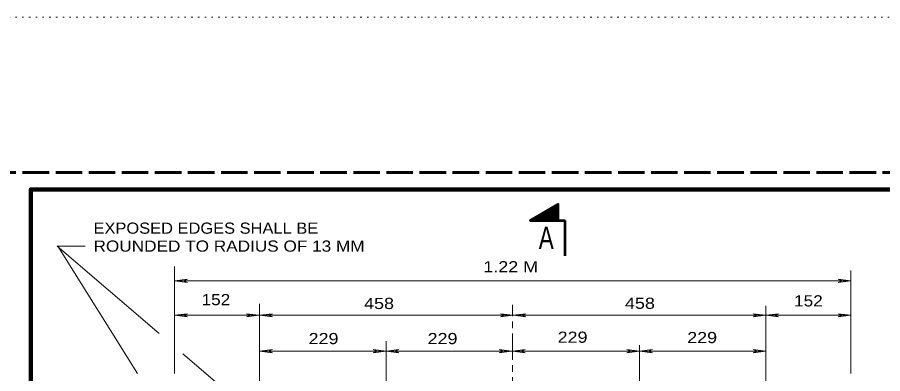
# Model space of a CAD drawing. Extents: x 312583 to 312854, y 144419 to 144597.
# Drawn here: x 312615.6 to 312674.5, y 144572.6 to 144596.8 of the extents above; entities that cross this region are included whole.
import ezdxf
from ezdxf.enums import TextEntityAlignment as Align

# ---------------------------------------------------------------- set-up
doc = ezdxf.new("R2010")
doc.units = 0
doc.header["$LTSCALE"] = 0.3
for name, pattern in [('DOTTED', [1.5, 0.3, -1.2]), ('LONG_DASH_SHORT_DASH', [9.9, 6, -1.2, 1.5, -1.2]), ('LONG_DASHED', [7.5, 6, -1.5])]:
    doc.linetypes.add(name, pattern=pattern)
for name, color, linetype, lineweight in [('1', 7, 'Continuous', 40), ('2', 7, 'Continuous', 13), ('63', 7, 'DOTTED', 13)]:
    doc.layers.add(name, color=color, linetype=linetype, lineweight=lineweight)

msp = doc.modelspace()

# ---------------------------------------------------------------- linework, layer by layer
at = {"layer": '1', "linetype": 'LONG_DASHED', "lineweight": 60}
msp.add_line((312851.75, 144586.2246), (312583.526, 144586.2246), dxfattribs=at)
at = {"layer": '1', "lineweight": 35}
for p, q in [((312652.3828, 144583.3724), (312652.0761, 144583.9014)), ((312652.3828, 144583.4184), (312652.0991, 144583.9091)), ((312652.3828, 144583.4721), (312652.1144, 144583.9244)), ((312652.3828, 144583.5181), (312652.1374, 144583.9321)), ((312652.3828, 144583.5641), (312652.1604, 144583.9474)), ((312652.3828, 144583.6178), (312652.1758, 144583.9551)), ((312652.3828, 144583.6638), (312652.2064, 144583.9704)), ((312652.3828, 144583.7098), (312652.2218, 144583.9781)), ((312652.3828, 144583.7558), (312652.2448, 144583.9934)), ((312652.3828, 144583.8094), (312652.2678, 144584.0011)), ((312652.3828, 144583.8478), (312652.2831, 144584.0164)), ((312652.3828, 144583.9014), (312652.3061, 144584.0241)), ((312652.3828, 144583.9474), (312652.3291, 144584.0394)), ((312652.3828, 144584.0011), (312652.3444, 144584.0548)), ((312652.3828, 144584.0471), (312652.3674, 144584.0624)), ((312651.2864, 144582.9661), (312651.0794, 144583.3264)), ((312651.3094, 144582.9661), (312651.1024, 144583.3341)), ((312651.3401, 144582.9661), (312651.1254, 144583.3494)), ((312651.3708, 144582.9661), (312651.1408, 144583.3648)), ((312651.4014, 144582.9661), (312651.1638, 144583.3724)), ((312651.4244, 144582.9661), (312651.1868, 144583.3878)), ((312651.4474, 144582.9661), (312651.2098, 144583.3954)), ((312651.4781, 144582.9661), (312651.2251, 144583.4108)), ((312651.5088, 144582.9661), (312651.2481, 144583.4184)), ((312651.5318, 144582.9661), (312651.2711, 144583.4338)), ((312651.5624, 144582.9661), (312651.2864, 144583.4414)), ((312651.5931, 144582.9661), (312651.3094, 144583.4568)), ((312651.6161, 144582.9661), (312651.3324, 144583.4644)), ((312651.6468, 144582.9661), (312651.3478, 144583.4798)), ((312651.6774, 144582.9661), (312651.3708, 144583.4874)), ((312651.7004, 144582.9661), (312651.3938, 144583.5028)), ((312651.7311, 144582.9738), (312651.4091, 144583.5181)), ((312651.7541, 144582.9661), (312651.4398, 144583.5258)), ((312651.7848, 144582.9661), (312651.4551, 144583.5411)), ((312651.8078, 144582.9661), (312651.4781, 144583.5488)), ((312651.8384, 144582.9661), (312651.5011, 144583.5641)), ((312651.8691, 144582.9661), (312651.5164, 144583.5718)), ((312651.8998, 144582.9661), (312651.5394, 144583.5871)), ((312651.9228, 144582.9661), (312651.5624, 144583.5948)), ((312651.9458, 144582.9661), (312651.5778, 144583.6101)), ((312651.9764, 144582.9738), (312651.6008, 144583.6178)), ((312652.0071, 144582.9661), (312651.6238, 144583.6331)), ((312652.0301, 144582.9661), (312651.6391, 144583.6408)), ((312652.0608, 144582.9661), (312651.6621, 144583.6561)), ((312652.0914, 144582.9661), (312651.6851, 144583.6714)), ((312652.1144, 144582.9661), (312651.7081, 144583.6791)), ((312652.1451, 144582.9661), (312651.7234, 144583.6944)), ((312652.1758, 144582.9661), (312651.7464, 144583.7098)), ((312652.1988, 144582.9738), (312651.7694, 144583.7174)), ((312652.2294, 144582.9738), (312651.7848, 144583.7328)), ((312652.2524, 144582.9661), (312651.8078, 144583.7404)), ((312652.2831, 144582.9661), (312651.8308, 144583.7558)), ((312652.3061, 144582.9661), (312651.8461, 144583.7634)), ((312652.3368, 144582.9661), (312651.8691, 144583.7788)), ((312652.3674, 144582.9661), (312651.8921, 144583.7864)), ((312652.3828, 144582.9891), (312651.9074, 144583.8018)), ((312652.3828, 144583.0428), (312651.9381, 144583.8094)), ((312652.3828, 144583.0811), (312651.9534, 144583.8248)), ((312652.3828, 144583.1348), (312651.9764, 144583.8324)), ((312652.3828, 144583.1808), (312651.9994, 144583.8478)), ((312652.3828, 144583.2268), (312652.0148, 144583.8631)), ((312652.3828, 144583.2728), (312652.0378, 144583.8708)), ((312652.3828, 144583.3264), (312652.0608, 144583.8861)), ((312650.4814, 144582.9661), (312650.4814, 144582.9814)), ((312650.5121, 144582.9661), (312650.5044, 144582.9891)), ((312650.5428, 144582.9661), (312650.5198, 144583.0044)), ((312650.5658, 144582.9661), (312650.5428, 144583.0121)), ((312650.5964, 144582.9661), (312650.5658, 144583.0274)), ((312650.6194, 144582.9661), (312650.5811, 144583.0351)), ((312650.6501, 144582.9661), (312650.6041, 144583.0504)), ((312650.6808, 144582.9661), (312650.6271, 144583.0581)), ((312650.7114, 144582.9661), (312650.6424, 144583.0734)), ((312650.7344, 144582.9661), (312650.6654, 144583.0811)), ((312650.7574, 144582.9661), (312650.6884, 144583.0964)), ((312650.7881, 144582.9661), (312650.7114, 144583.1041)), ((312650.8111, 144582.9661), (312650.7268, 144583.1194)), ((312650.8418, 144582.9661), (312650.7498, 144583.1348)), ((312650.8724, 144582.9661), (312650.7728, 144583.1424)), ((312650.9031, 144582.9661), (312650.7881, 144583.1578)), ((312650.9261, 144582.9661), (312650.8111, 144583.1731)), ((312650.9568, 144582.9661), (312650.8341, 144583.1808)), ((312650.9798, 144582.9661), (312650.8494, 144583.1961)), ((312651.0104, 144582.9661), (312650.8724, 144583.2038)), ((312651.0411, 144582.9661), (312650.8954, 144583.2191)), ((312651.0641, 144582.9661), (312650.9108, 144583.2268)), ((312651.0948, 144582.9661), (312650.9414, 144583.2421)), ((312651.1178, 144582.9661), (312650.9568, 144583.2498)), ((312651.1484, 144582.9661), (312650.9798, 144583.2651)), ((312651.1791, 144582.9661), (312651.0028, 144583.2728)), ((312651.2021, 144582.9661), (312651.0181, 144583.2881)), ((312651.2328, 144582.9661), (312651.0411, 144583.2958)), ((312651.2558, 144582.9661), (312651.0641, 144583.3111))]:
    msp.add_line(p, q, dxfattribs=at)
at = {"layer": '1', "lineweight": 53}
for p in [(312652.3828, 144582.9661), (312652.8581, 144580.5741)]:
    msp.add_line(p, (312652.8581, 144582.9661), dxfattribs=at)
at = {"layer": '1', "lineweight": 158}
msp.add_lwpolyline([(312616.5, 144423.1446), (312616.5, 144585.0846), (312849, 144585.0846)], dxfattribs=at)
at = {"layer": '1', "lineweight": 53}
msp.add_lwpolyline([(312652.3828, 144582.9661), (312652.3828, 144584.0778), (312650.4661, 144582.9661)], close=True, dxfattribs=at)
at = {"layer": '2'}
for p, q in [((312618.3476, 144581.2339), (312623.7708, 144572.5701)), ((312626.2931, 144572.5701), (312626.2931, 144579.8458)), ((312672.2931, 144572.5701), (312672.2931, 144579.5698)), ((312626.2931, 144578.8721), (312627.1594, 144578.9794)), ((312626.2931, 144578.8721), (312672.2931, 144578.8721)), ((312626.2931, 144578.8721), (312627.1594, 144578.7648)), ((312627.1594, 144578.9794), (312626.8834, 144578.8721)), ((312627.1594, 144578.7648), (312626.8834, 144578.8721)), ((312671.4268, 144578.9794), (312671.7028, 144578.8721)), ((312672.2931, 144578.8721), (312671.4268, 144578.9794)), ((312671.4268, 144578.7648), (312671.7028, 144578.8721)), ((312672.2931, 144578.8721), (312671.4268, 144578.7648)), ((312632.0738, 144566.5824), (312632.0738, 144577.3004)), ((312666.4971, 144566.4981), (312666.4971, 144577.1778)), ((312626.2931, 144576.5261), (312627.1594, 144576.6334)), ((312626.2931, 144576.5261), (312632.0431, 144576.5261)), ((312626.2931, 144576.5261), (312627.1594, 144576.4188)), ((312627.1594, 144576.6334), (312626.8834, 144576.5261)), ((312627.1594, 144576.4188), (312626.8834, 144576.5261)), ((312631.1768, 144576.6334), (312631.4528, 144576.5261)), ((312632.0431, 144576.5261), (312631.1768, 144576.6334)), ((312631.1768, 144576.4188), (312631.4528, 144576.5261)), ((312632.0431, 144576.5261), (312631.1768, 144576.4188)), ((312632.0738, 144576.5261), (312632.9401, 144576.6334)), ((312632.0738, 144576.5261), (312649.3161, 144576.5261)), ((312632.0738, 144576.5261), (312632.9401, 144576.4188)), ((312632.9401, 144576.6334), (312632.6641, 144576.5261)), ((312632.9401, 144576.4188), (312632.6641, 144576.5261)), ((312648.4498, 144576.6334), (312648.7258, 144576.5261)), ((312649.3161, 144576.5261), (312648.4498, 144576.6334)), ((312648.4498, 144576.4188), (312648.7258, 144576.5261)), ((312649.3161, 144576.5261), (312648.4498, 144576.4188)), ((312649.3161, 144576.5261), (312650.1824, 144576.6334)), ((312649.3161, 144576.5261), (312666.4971, 144576.5261)), ((312649.3161, 144576.5261), (312650.1824, 144576.4188)), ((312650.1824, 144576.6334), (312649.9064, 144576.5261)), ((312650.1824, 144576.4188), (312649.9064, 144576.5261)), ((312665.6308, 144576.6334), (312665.9068, 144576.5261)), ((312666.4971, 144576.5261), (312665.6308, 144576.6334)), ((312665.6308, 144576.4188), (312665.9068, 144576.5261)), ((312666.4971, 144576.5261), (312665.6308, 144576.4188)), ((312666.4971, 144576.5261), (312667.3634, 144576.6334)), ((312666.4971, 144576.5261), (312672.2931, 144576.5261)), ((312666.4971, 144576.5261), (312667.3634, 144576.4188)), ((312667.3634, 144576.6334), (312667.0874, 144576.5261)), ((312667.3634, 144576.4188), (312667.0874, 144576.5261)), ((312671.4268, 144576.6334), (312671.7028, 144576.5261)), ((312672.2931, 144576.5261), (312671.4268, 144576.6334)), ((312671.4268, 144576.4188), (312671.7028, 144576.5261)), ((312672.2931, 144576.5261), (312671.4268, 144576.4188)), ((312640.6681, 144569.5264), (312640.6681, 144574.7551)), ((312626.8451, 144573.9118), (312629.2064, 144571.8954)), ((312632.0738, 144574.0804), (312632.9401, 144574.1878)), ((312632.0738, 144574.0804), (312640.6681, 144574.0804)), ((312632.0738, 144574.0804), (312632.9401, 144573.9731)), ((312632.9401, 144574.1878), (312632.6641, 144574.0804)), ((312632.9401, 144573.9731), (312632.6641, 144574.0804)), ((312639.8018, 144574.1878), (312640.0778, 144574.0804)), ((312640.6681, 144574.0804), (312639.8018, 144574.1878)), ((312639.8018, 144573.9731), (312640.0778, 144574.0804)), ((312640.6681, 144574.0804), (312639.8018, 144573.9731)), ((312640.6834, 144574.0804), (312641.5498, 144574.1878)), ((312640.6834, 144574.0804), (312649.2318, 144574.0804)), ((312640.6834, 144574.0804), (312641.5498, 144573.9731)), ((312641.5498, 144574.1878), (312641.2738, 144574.0804)), ((312641.5498, 144573.9731), (312641.2738, 144574.0804)), ((312648.3654, 144574.1878), (312648.6414, 144574.0804)), ((312649.2318, 144574.0804), (312648.3654, 144574.1878)), ((312648.3654, 144573.9731), (312648.6414, 144574.0804)), ((312649.2318, 144574.0804), (312648.3654, 144573.9731)), ((312649.2701, 144574.0804), (312650.1364, 144574.1878)), ((312649.2701, 144574.0804), (312657.9181, 144574.0804)), ((312649.2701, 144574.0804), (312650.1364, 144573.9731)), ((312650.1364, 144574.1878), (312649.8604, 144574.0804)), ((312650.1364, 144573.9731), (312649.8604, 144574.0804)), ((312657.0518, 144574.1878), (312657.3278, 144574.0804)), ((312657.9181, 144574.0804), (312657.0518, 144574.1878)), ((312657.0518, 144573.9731), (312657.3278, 144574.0804)), ((312657.9181, 144574.0804), (312657.0518, 144573.9731)), ((312657.9181, 144574.0804), (312658.7844, 144574.1878)), ((312657.9181, 144574.0804), (312666.4971, 144574.0804)), ((312657.9181, 144574.0804), (312658.7844, 144573.9731)), ((312658.7844, 144574.1878), (312658.5084, 144574.0804)), ((312658.7844, 144573.9731), (312658.5084, 144574.0804)), ((312665.6308, 144574.1878), (312665.9068, 144574.0804)), ((312666.4971, 144574.0804), (312665.6308, 144574.1878)), ((312665.6308, 144573.9731), (312665.9068, 144574.0804)), ((312666.4971, 144574.0804), (312665.6308, 144573.9731))]:
    msp.add_line(p, q, dxfattribs=at)
at = {"layer": '2', "linetype": 'LONG_DASH_SHORT_DASH'}
msp.add_line((312649.2624, 144558.6398), (312649.2624, 144577.2468), dxfattribs=at)
at = {"layer": '2'}
for points in [[(312620.2134, 144581.2339), (312618.2911, 144581.2339), (312625.2428, 144575.2918)], [(312657.9181, 144569.5264), (312657.9181, 144574.0958), (312657.9181, 144574.4868)]]:
    msp.add_lwpolyline(points, dxfattribs=at)
at = {"layer": '63'}
msp.add_line((312601.2, 144596.7846), (312853.5, 144596.7846), dxfattribs=at)

# ---------------------------------------------------------------- texts
at = {"layer": '1'}
for s, width, p in [('EXPOSED EDGES SHALL BE', 1.1, (312620.7731, 144582.07)), ('ROUNDED TO RADIUS OF 13 MM', 1.15, (312620.7731, 144580.85)), ('152 ', 1.15, (312628.1226, 144577.2113)), ('458 ', 1.2, (312639.1781, 144576.9506)), ('458 ', 1.2, (312656.9237, 144576.964)), ('152 ', 1.15, (312668.4244, 144577.1269)), ('229 ', 1.2, (312635.4018, 144574.5625)), ('229 ', 1.2, (312643.4963, 144574.5625)), ('229 ', 1.2, (312652.34, 144574.6545)), ('229 ', 1.2, (312661.1527, 144574.6315))]:
    msp.add_text(s, height=0.76, dxfattribs=dict(at, width=width)).set_placement(p)
at = {"layer": '1', "width": 0.75}
msp.add_text('A', height=1.533, dxfattribs=at).set_placement((312651.5663, 144581.0264), align=Align.CENTER)
at = {"layer": '2', "width": 1.2}
msp.add_text('1.22 M', height=0.76, dxfattribs=at).set_placement((312647.2878, 144579.4443))

doc.saveas('drawing.dxf')
